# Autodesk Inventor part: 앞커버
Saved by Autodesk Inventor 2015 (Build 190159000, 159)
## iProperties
Created: 2025-08
Part Number: 앞커버
Material: 일반
Document SubType Name: Modeling
Designer: USER
Density: 1 g/cm^3
Appearance: 기본값
Author: USER
Author: jhkim
Creation Date: 2025-08-05
Sending System: Autodesk Inventor 2026
Preprocessor: ST-DEVELOPER v20.1
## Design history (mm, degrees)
node "앞커버1"
node "솔리드1"
node "기준1"
